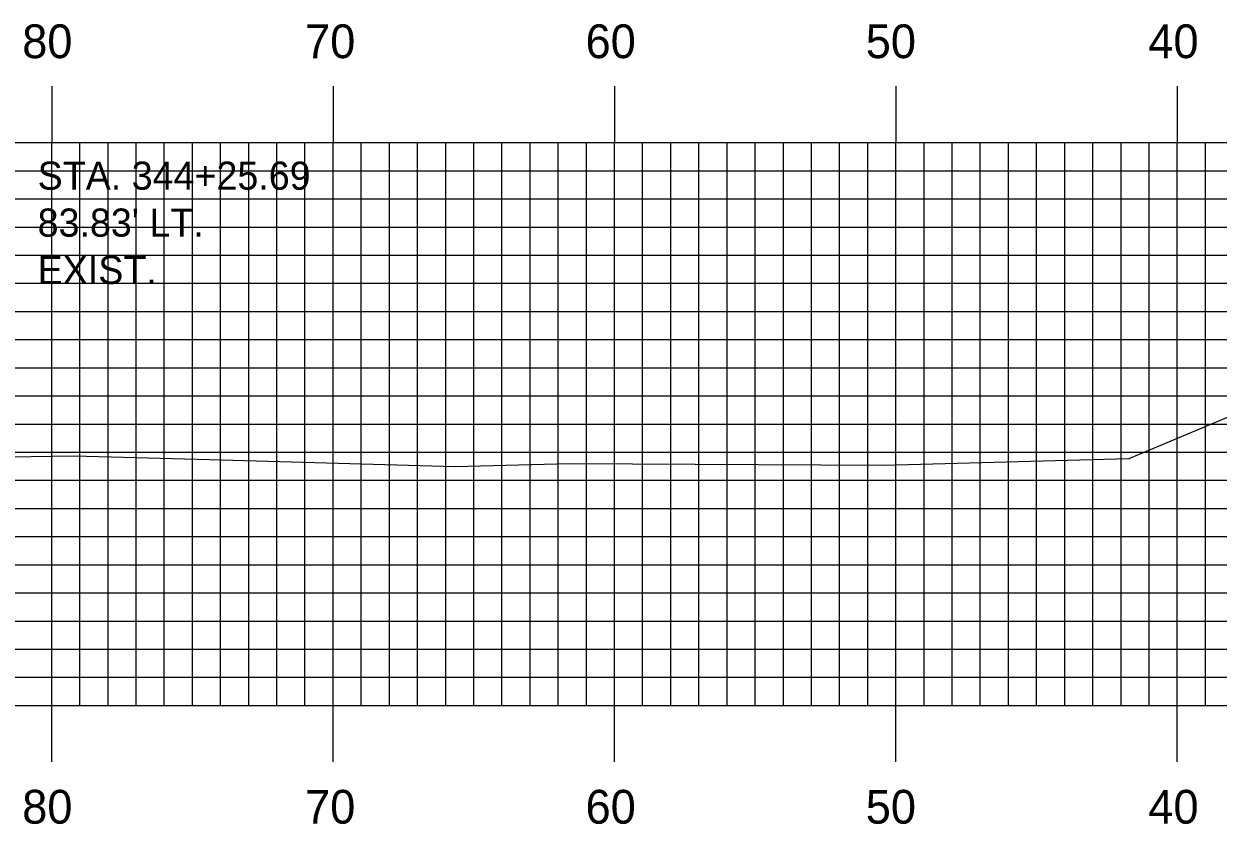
# Model space of a CAD drawing. Extents: x 1825540 to 1825883, y 442591 to 442811.
# Drawn here: x 1825624.88 to 1825667.33, y 442654.45 to 442682.88 of the extents above; entities that cross this region are included whole.
import ezdxf

# ---------------------------------------------------------------- set-up
doc = ezdxf.new("R2010")
doc.units = 0
for name, color, linetype in [('D_Text_Monospaced', 7, 'Continuous'), ('H_V ANNOTATION', 7, 'Continuous'), ('MAJOR', 7, 'Continuous'), ('MINOR', 7, 'Continuous'), ('S_Roadway_Centerline', 7, 'Continuous')]:
    doc.layers.add(name, color=color, linetype=linetype)

msp = doc.modelspace()

# ---------------------------------------------------------------- linework, layer by layer
at = {"layer": 'MAJOR'}
for p, q in [((1825625.874, 442680.669), (1825625.874, 442678.665)), ((1825635.874, 442680.669), (1825635.874, 442678.665)), ((1825645.874, 442680.669), (1825645.874, 442678.665)), ((1825655.874, 442680.669), (1825655.874, 442678.665)), ((1825665.874, 442680.669), (1825665.874, 442678.665)), ((1825565.874, 442678.665), (1825845.874, 442678.665)), ((1825565.874, 442678.665), (1825845.874, 442678.665)), ((1825625.874, 442658.665), (1825625.874, 442678.665)), ((1825635.874, 442658.665), (1825635.874, 442678.665)), ((1825645.874, 442658.665), (1825645.874, 442678.665)), ((1825655.874, 442658.665), (1825655.874, 442678.665)), ((1825665.874, 442658.665), (1825665.874, 442678.665)), ((1825565.874, 442673.665), (1825845.874, 442673.665)), ((1825565.874, 442668.665), (1825845.874, 442668.665)), ((1825565.874, 442663.665), (1825845.874, 442663.665)), ((1825565.874, 442658.665), (1825845.874, 442658.665)), ((1825565.874, 442658.665), (1825845.874, 442658.665)), ((1825625.874, 442656.661), (1825625.874, 442658.665)), ((1825635.874, 442656.661), (1825635.874, 442658.665)), ((1825645.874, 442656.661), (1825645.874, 442658.665)), ((1825655.874, 442656.661), (1825655.874, 442658.665)), ((1825665.874, 442656.661), (1825665.874, 442658.665))]:
    msp.add_line(p, q, dxfattribs=at)
at = {"layer": 'MINOR'}
for p, q in [((1825626.874, 442658.665), (1825626.874, 442678.665)), ((1825627.874, 442658.665), (1825627.874, 442678.665)), ((1825628.874, 442658.665), (1825628.874, 442678.665)), ((1825629.874, 442658.665), (1825629.874, 442678.665)), ((1825630.874, 442658.665), (1825630.874, 442678.665)), ((1825631.874, 442658.665), (1825631.874, 442678.665)), ((1825632.874, 442658.665), (1825632.874, 442678.665)), ((1825633.874, 442658.665), (1825633.874, 442678.665)), ((1825634.874, 442658.665), (1825634.874, 442678.665)), ((1825636.874, 442658.665), (1825636.874, 442678.665)), ((1825637.874, 442658.665), (1825637.874, 442678.665)), ((1825638.874, 442658.665), (1825638.874, 442678.665)), ((1825639.874, 442658.665), (1825639.874, 442678.665)), ((1825640.874, 442658.665), (1825640.874, 442678.665)), ((1825641.874, 442658.665), (1825641.874, 442678.665)), ((1825642.874, 442658.665), (1825642.874, 442678.665)), ((1825643.874, 442658.665), (1825643.874, 442678.665)), ((1825644.874, 442658.665), (1825644.874, 442678.665)), ((1825646.874, 442658.665), (1825646.874, 442678.665)), ((1825647.874, 442658.665), (1825647.874, 442678.665)), ((1825648.874, 442658.665), (1825648.874, 442678.665)), ((1825649.874, 442658.665), (1825649.874, 442678.665)), ((1825650.874, 442658.665), (1825650.874, 442678.665)), ((1825651.874, 442658.665), (1825651.874, 442678.665)), ((1825652.874, 442658.665), (1825652.874, 442678.665)), ((1825653.874, 442658.665), (1825653.874, 442678.665)), ((1825654.874, 442658.665), (1825654.874, 442678.665)), ((1825656.874, 442658.665), (1825656.874, 442678.665)), ((1825657.874, 442658.665), (1825657.874, 442678.665)), ((1825658.874, 442658.665), (1825658.874, 442678.665)), ((1825659.874, 442658.665), (1825659.874, 442678.665)), ((1825660.874, 442658.665), (1825660.874, 442678.665)), ((1825661.874, 442658.665), (1825661.874, 442678.665)), ((1825662.874, 442658.665), (1825662.874, 442678.665)), ((1825663.874, 442658.665), (1825663.874, 442678.665)), ((1825664.874, 442658.665), (1825664.874, 442678.665)), ((1825666.874, 442658.665), (1825666.874, 442678.665)), ((1825565.874, 442677.665), (1825845.874, 442677.665)), ((1825565.874, 442676.665), (1825845.874, 442676.665)), ((1825565.874, 442675.665), (1825845.874, 442675.665)), ((1825565.874, 442674.665), (1825845.874, 442674.665)), ((1825565.874, 442672.665), (1825845.874, 442672.665)), ((1825565.874, 442671.665), (1825845.874, 442671.665)), ((1825565.874, 442670.665), (1825845.874, 442670.665)), ((1825565.874, 442669.665), (1825845.874, 442669.665)), ((1825565.874, 442667.665), (1825845.874, 442667.665)), ((1825565.874, 442666.665), (1825845.874, 442666.665)), ((1825565.874, 442665.665), (1825845.874, 442665.665)), ((1825565.874, 442664.665), (1825845.874, 442664.665)), ((1825565.874, 442662.665), (1825845.874, 442662.665)), ((1825565.874, 442661.665), (1825845.874, 442661.665)), ((1825565.874, 442660.665), (1825845.874, 442660.665)), ((1825565.874, 442659.665), (1825845.874, 442659.665))]:
    msp.add_line(p, q, dxfattribs=at)
at = {"layer": 'S_Roadway_Centerline'}
msp.add_lwpolyline([(1825620.521, 442667.443), (1825626.675, 442667.534), (1825631.476, 442667.401), (1825640.206, 442667.151), (1825644.272, 442667.261), (1825655.442, 442667.197), (1825664.148, 442667.443), (1825664.164, 442667.443), (1825664.173, 442667.443), (1825664.184, 442667.447), (1825672.039, 442670.745)], dxfattribs=at)

# ---------------------------------------------------------------- texts
at = {"layer": 'D_Text_Monospaced'}
for s, height, p in [('STA. 344+25.69', 0.99996, (1825625.373, 442676.99)), ("83.83' LT.", 1, (1825625.373, 442675.322)), ('EXIST. ', 1, (1825625.373, 442673.642))]:
    msp.add_text(s, height=height, dxfattribs=at).set_placement(p)
at = {"layer": 'H_V ANNOTATION'}
for s, p in [('80', (1825624.825, 442681.665)), ('70', (1825634.878, 442681.665)), ('60', (1825644.846, 442681.665)), ('50', (1825654.803, 442681.665)), ('40', (1825664.846, 442681.665)), ('80', (1825624.825, 442654.465)), ('70', (1825634.878, 442654.465)), ('60', (1825644.846, 442654.465)), ('50', (1825654.803, 442654.465)), ('40', (1825664.846, 442654.465))]:
    msp.add_text(s, height=1.2, dxfattribs=at).set_placement(p)

doc.saveas('drawing.dxf')
